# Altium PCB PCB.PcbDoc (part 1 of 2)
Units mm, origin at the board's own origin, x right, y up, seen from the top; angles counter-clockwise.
Board outline 85 x 56 mm, 4 copper layers (TOP, GND, SIG, BOTTOM), stack 1.586 mm thick; 75 components, 165 nets, 429 pads, 246 vias.
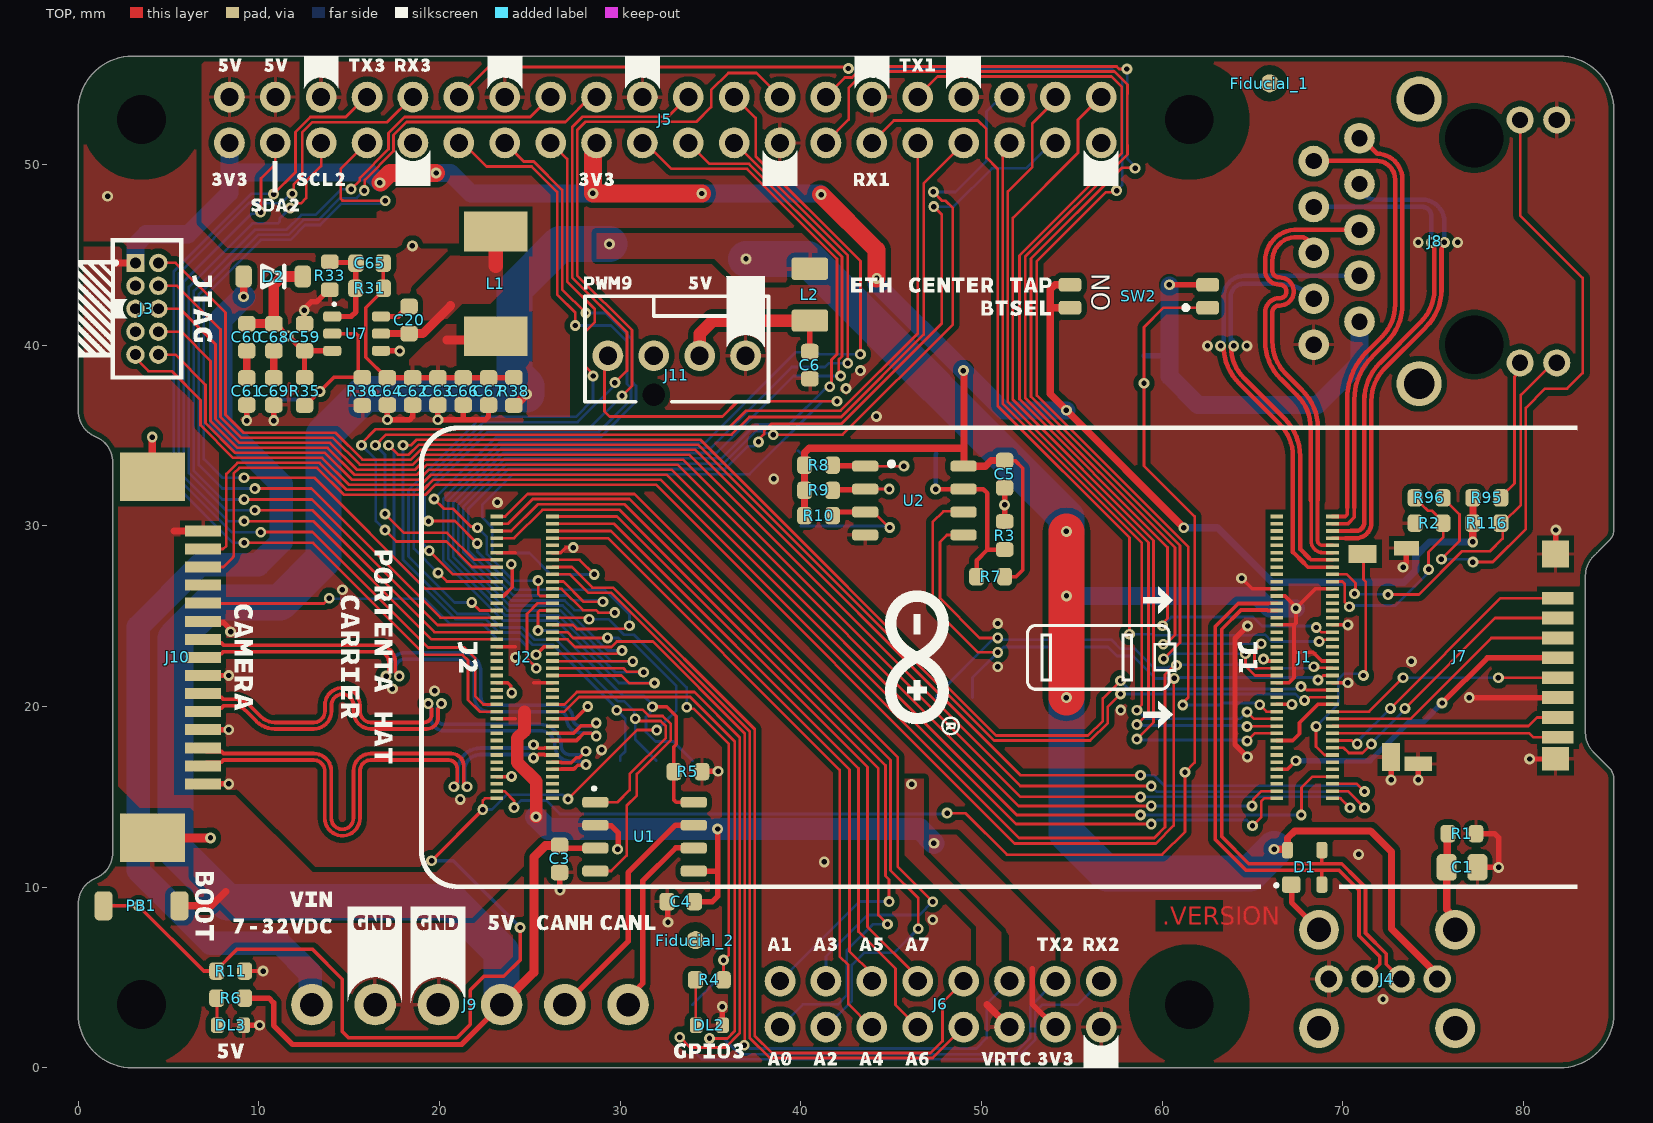
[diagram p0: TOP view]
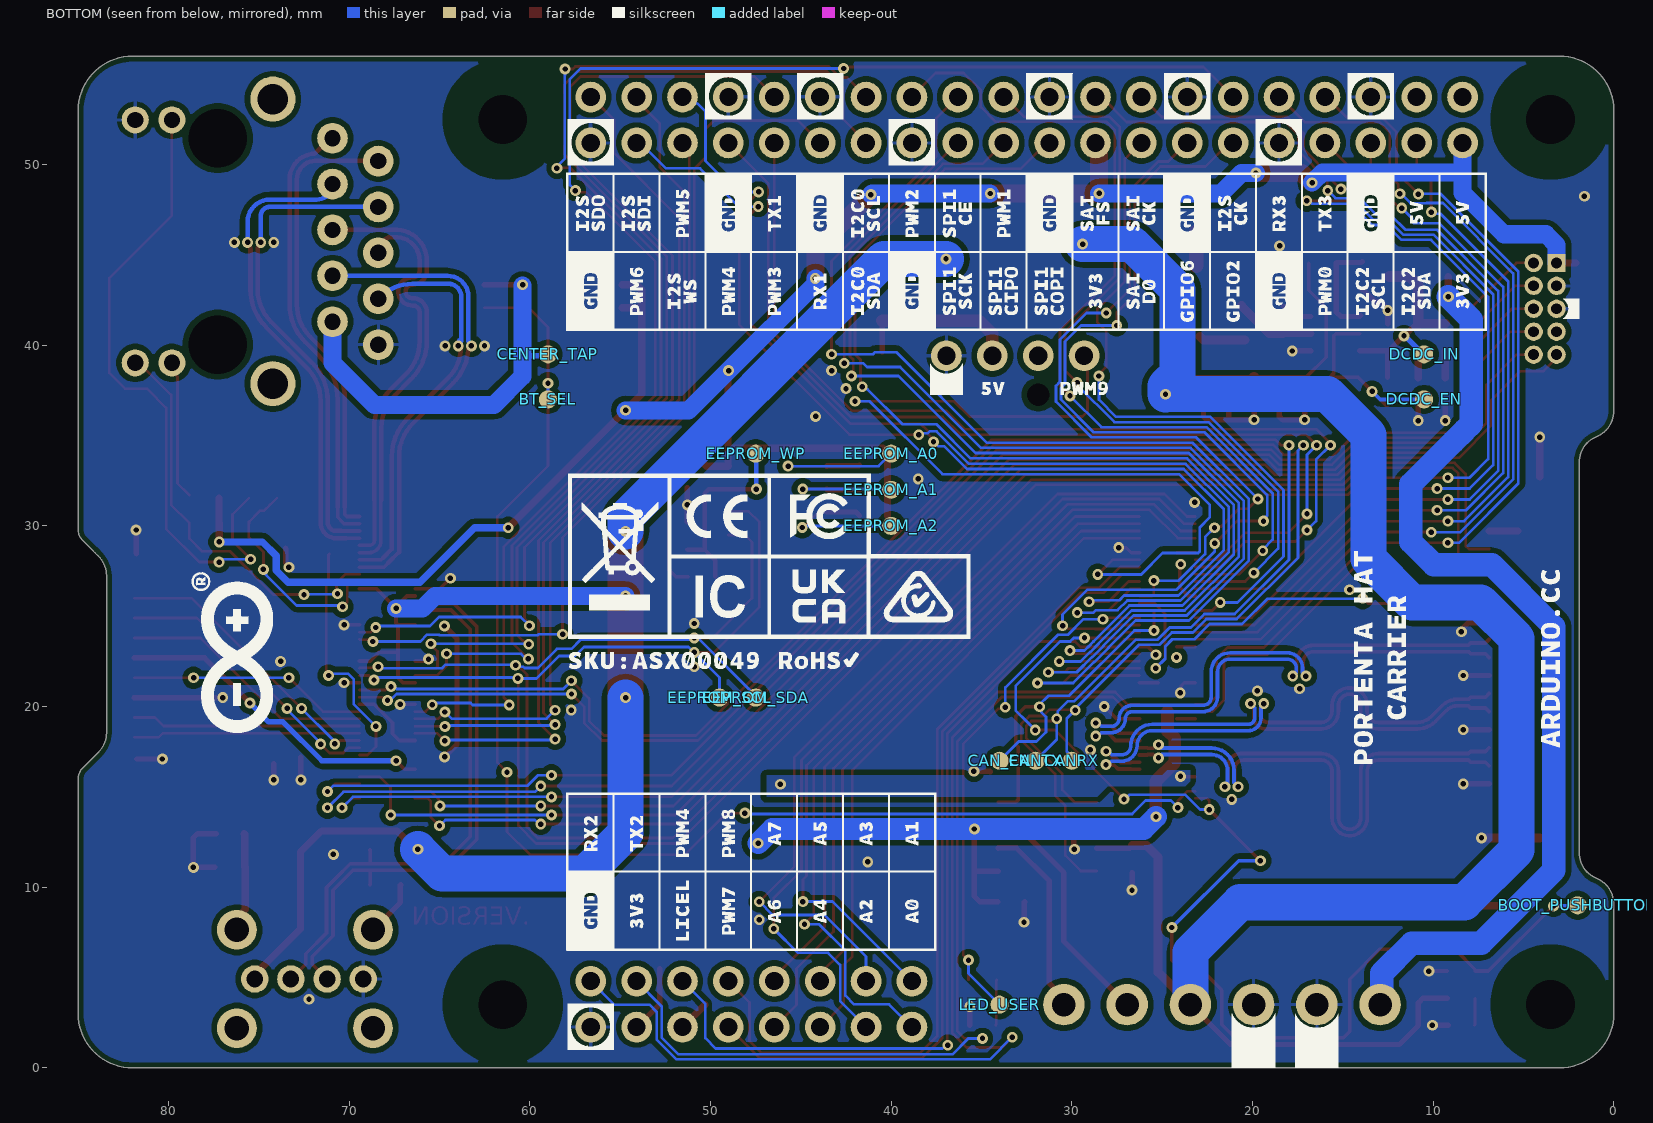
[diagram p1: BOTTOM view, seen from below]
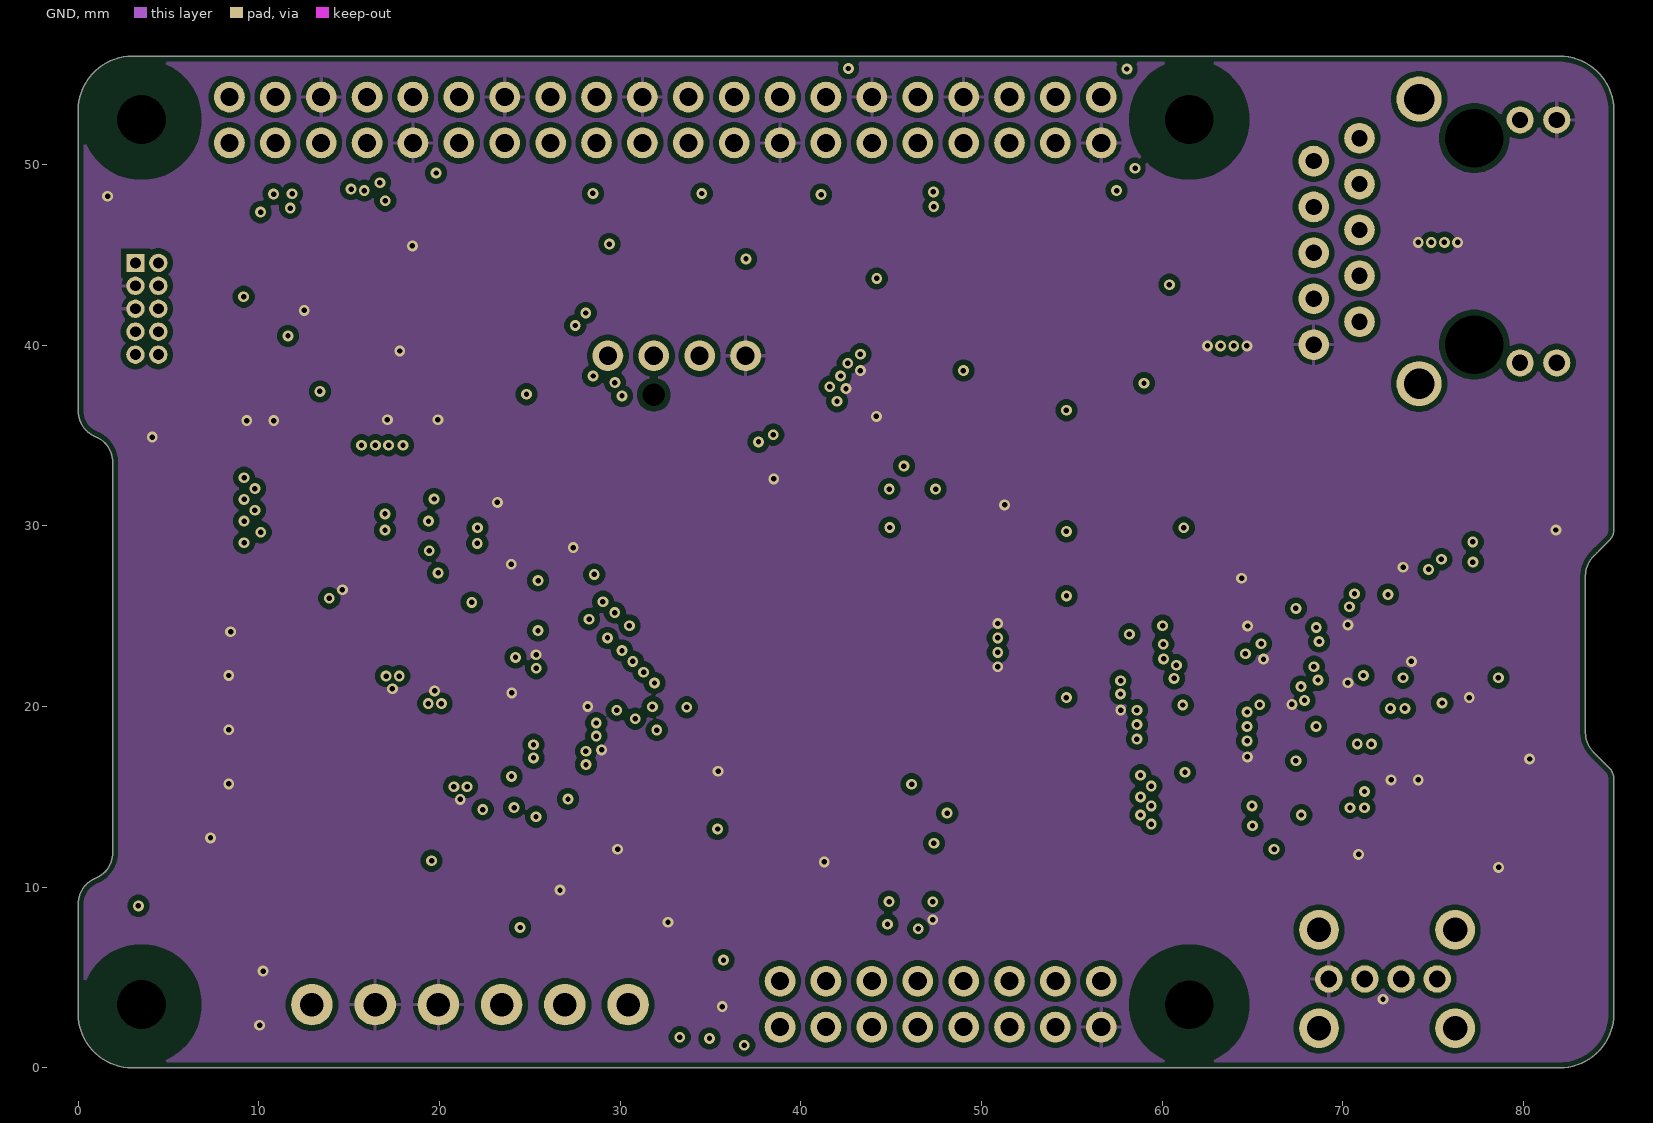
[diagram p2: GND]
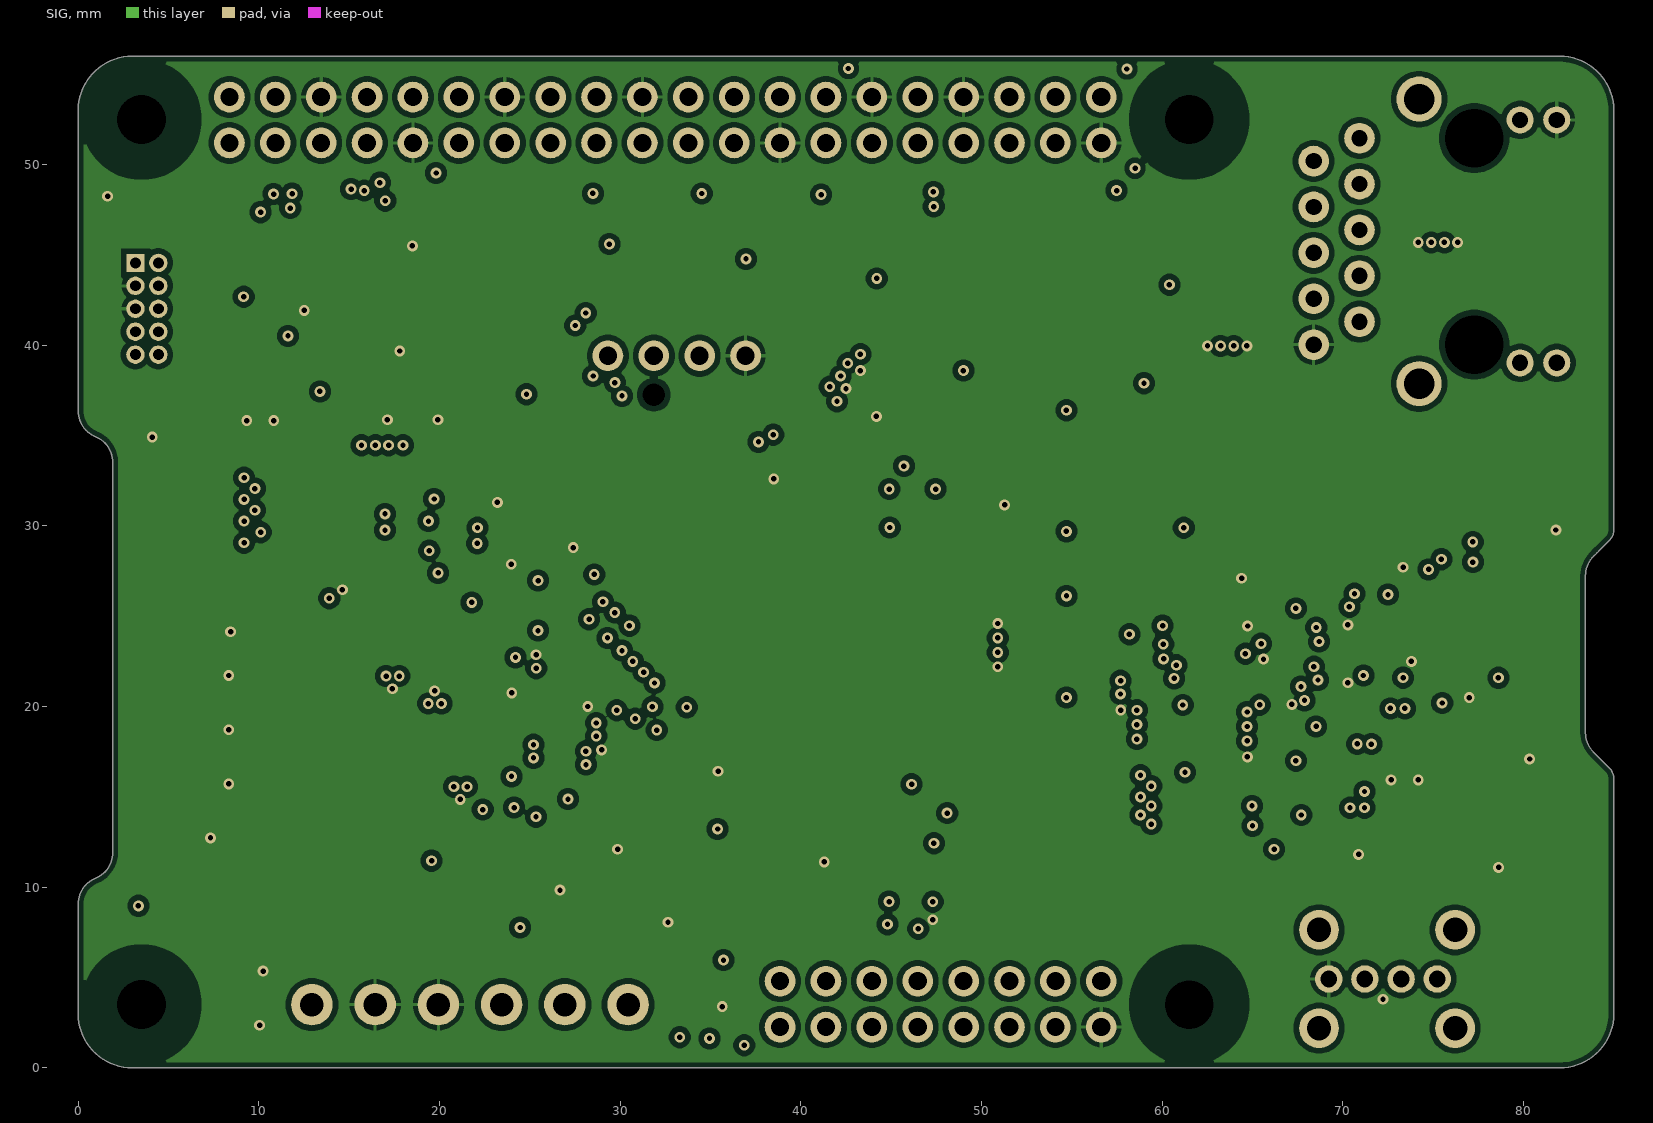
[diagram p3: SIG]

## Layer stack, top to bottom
Top Solder: solder mask 0.01, Solder Resist, Dk 3.5
TOP: signal copper 0.018
Dielectric 1: prepreg 0.14, PP-014, Dk 4.2
GND: signal copper 0.035
Dielectric2: core 1.2, FR-4, Dk 4.8
SIG: signal copper 0.035
Dielectric3: prepreg 0.14, PP-014, Dk 4.2
BOTTOM: signal copper 0.018
Bottom Solder: solder mask 0.01, Solder Resist, Dk 3.5

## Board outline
0,3 0,9.077 cw(c1.533,9.077) 0.959,10.499 ccw(c0.384,11.92) 1.917,11.92 1.917,33.52 ccw(c0.384,33.52) 0.959,34.941 cw(c1.533,36.363) 0,36.363 0,53 cw(c3,53) 3,56 82,56 82,55.999 cw(c82,52.999) 85,52.999 85,29.779 cw(c84.191,29.779) 84.763,29.207 84.251,28.695 84.065,28.509 83.879,28.323 ccw(c84.963,27.239) 83.43,27.239 83.43,18.559 ccw(c84.963,18.559) 83.879,17.475 84.763,16.591 cw(c84.191,16.019) 85,16.019 85,3 cw(c82,3) 82,0 3,0 cw(c3,3)

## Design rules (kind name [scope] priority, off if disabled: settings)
BoardOutlineClearance Mousebites [(ObjectKind = 'Pad') And (Name = 'Free-MOUSEBITE')] p1: gap=0 ignorepadtopadclearanceinfootprint=FALSE
BoardOutlineClearance eth_PAD [(ObjectKind = 'Pad') And (Name = 'J8-S2')] p2: gap=0.1 ignorepadtopadclearanceinfootprint=FALSE
BoardOutlineClearance Silks [(OnLayer('Top Overlay') OR OnLayer('Bottom Overlay'))] p3: gap=0 ignorepadtopadclearanceinfootprint=FALSE
BoardOutlineClearance [All] p4: gap=0.3 ignorepadtopadclearanceinfootprint=FALSE
Clearance Fixing [(ObjectKind = 'Pad') And (Layer = 'MultiLayer') And (Name = 'Free-FIXING')] p1: gap=2 ignorepadtopadclearanceinfootprint=FALSE
Clearance COPPER_0.3mm [All] p2: gap=0.127 ignorepadtopadclearanceinfootprint=TRUE except(0.3: Arc-Fill Arc-Poly Arc-Region Track-Fill Track-Poly Track-Region SMDPad-Fill SMDPad-Poly SMDPad-Region THPad-Fill THPad-Poly THPad-Region Via-Fill Via-Poly Via-Region Fill-Fill Fill-Poly Fill-Region Poly-Poly Poly-Region Region-Region)
Clearance "Generic clearance 0.15mm" [All] p3: gap=0.15 ignorepadtopadclearanceinfootprint=TRUE
ComponentClearance [All] p1: gap=0.2 collisioncheckmode=3 verticalgap=0 showdistances=TRUE
DiffPairsRouting ETH [InDifferentialPairClass('ETH')] p1: maxlimit=0.15 minlimit=0.15 mostfreqgap=0.15 toplayer_minwidth=0.15 toplayer_maxwidth=0.25 toplayer_prefwidth=0.25 midlayer1_minwidth=0.15 midlayer1_maxwidth=0.381 midlayer1_prefwidth=0.381 midlayer2_minwidth=0.15 midlayer2_maxwidth=0.381 midlayer2_prefwidth=0.381 bottomlayer_minwidth=0.15 bottomlayer_maxwidth=0.25 bottomlayer_prefwidth=0.25 maxuncoupledlength=12.7
DiffPairsRouting USB [InDifferentialPairClass('USB')] p2: maxlimit=0.25 minlimit=0.15 mostfreqgap=0.25 toplayer_maxgap=0.15 toplayer_prefgap=0.15 toplayer_minwidth=0.15 toplayer_maxwidth=0.21 toplayer_prefwidth=0.21 midlayer2_mingap=0.25 midlayer2_minwidth=0.15 midlayer2_maxwidth=0.15 midlayer2_prefwidth=0.15 bottomlayer_maxgap=0.15 bottomlayer_prefgap=0.15 bottomlayer_minwidth=0.15 bottomlayer_maxwidth=0.21 bottomlayer_prefwidth=0.21 impedanceprofiledriven=TRUE impedanceprofileid={065E212C-32C3-402A-8E5D-A34D7F87B9C8} impedanceprofilevalue=90.000000 maxuncoupledlength=12.7
DiffPairsRouting CAM [InDifferentialPairClass('CAMERA')] p3: maxlimit=0.25 minlimit=0.15 mostfreqgap=0.25 toplayer_maxgap=0.15 toplayer_prefgap=0.15 toplayer_minwidth=0.15 toplayer_maxwidth=0.21 toplayer_prefwidth=0.21 midlayer2_mingap=0.25 midlayer2_minwidth=0.15 midlayer2_maxwidth=0.15 midlayer2_prefwidth=0.15 bottomlayer_maxgap=0.15 bottomlayer_prefgap=0.15 bottomlayer_minwidth=0.15 bottomlayer_maxwidth=0.21 bottomlayer_prefwidth=0.21 impedanceprofiledriven=TRUE impedanceprofileid={065E212C-32C3-402A-8E5D-A34D7F87B9C8} impedanceprofilevalue=90.000000 maxuncoupledlength=12.7
Height [All] p1: minheight=0 maxheight=30 prefheight=12.7
HoleSize [All] p1: absolutevalues=TRUE maxlimit=30 minlimit=0.3 maxpercent=80.000 minpercent=20.000
HoleToHoleClearance [All] p1: gap=0.25 allowstackedmicrovias=FALSE
MatchedLengths CAM_DIFF [InDifferentialPairClass('CAMERA')] p1: tolerance=25.4 checknetsindiffpair=FALSE checkdiffpairvsdiffpair=TRUE checkxsignals=TRUE checkothers=TRUE usedelayunits=TRUE delaytolerance=30.000000
MatchedLengths ETH_DIFF [InDifferentialPairClass('ETH')] p2: tolerance=25.4 checknetsindiffpair=TRUE checkdiffpairvsdiffpair=FALSE checkxsignals=FALSE checkothers=FALSE usedelayunits=TRUE delaytolerance=10.000000
MatchedLengths ETH_group [InDifferentialPairClass('ETH')] p3: tolerance=25.4 checknetsindiffpair=FALSE checkdiffpairvsdiffpair=TRUE checkxsignals=TRUE checkothers=TRUE usedelayunits=TRUE delaytolerance=10.000000
MinimumAnnularRing [All] p1: minimumring=0.15
PlaneConnect [All] p1: pad.planeconnectstyle=Relief pad.reliefexpansion=0.508 pad.reliefentries=4 pad.reliefconductorwidth=0.254 pad.reliefairgap=0.254 via.planeconnectstyle=Direct via.reliefexpansion=0.508 via.reliefentries=4 via.reliefconductorwidth=0.254 via.reliefairgap=0.254
PolygonConnect [All] p1: thpad.connectstyle=Relief thpad.reliefconductorwidth=0.2 thpad.reliefentries=4 thpad.polygonreliefangle="90 Angle" thpad.airgapwidth=0.254 smdpad.connectstyle=Relief smdpad.reliefconductorwidth=0.2 smdpad.reliefentries=4 smdpad.polygonreliefangle="90 Angle" smdpad.airgapwidth=0.254 via.connectstyle=Direct via.reliefconductorwidth=0.254 via.reliefentries=4 via.polygonreliefangle="90 Angle" via.airgapwidth=0.254
RoomDefinition U_EEPROM [InComponentClass('U_EEPROM')] p1: confinementstyle=ConfineIn formatcopy=TRUE lockcomponents=FALSE outline 86.162,1.499 112.562,1.499 112.562,9.999 86.162,9.999
RoomDefinition U_CAMERA [InComponentClass('U_CAMERA')] p2: confinementstyle=ConfineIn formatcopy=TRUE lockcomponents=FALSE outline 86.162,0.399 94.562,0.399 94.562,25.899 86.162,25.899
RoomDefinition DCDC_CONVERTER [InComponentClass('DCDC_CONVERTER')] p3: confinementstyle=ConfineIn formatcopy=TRUE lockcomponents=FALSE outline 86.162,0.499 88.762,0.499 88.762,6.799 86.162,6.799
RoomDefinition U_CAN_PHY [InComponentClass('U_CAN_PHY')] p4: confinementstyle=ConfineIn formatcopy=TRUE lockcomponents=FALSE outline 86.162,1.499 88.562,1.499 88.562,4.099 86.162,4.099
RoomDefinition U_ETH_CONNECTOR [InComponentClass('U_ETH_CONNECTOR')] p5: confinementstyle=ConfineIn formatcopy=TRUE lockcomponents=FALSE outline 86.162,1.499 147.662,1.499 147.662,27.099 86.162,27.099
RoomDefinition U_SDcard [InComponentClass('U_SDcard')] p6: confinementstyle=ConfineIn formatcopy=TRUE lockcomponents=FALSE outline -25.538,-7.701 25.262,-7.701 25.262,17.699 -25.538,17.699
RoomDefinition "MICRO USB CONNECTOR" [InComponentClass('MICRO USB CONNECTOR')] p7: confinementstyle=ConfineIn formatcopy=TRUE lockcomponents=FALSE outline 66.762,22.299 84.462,22.299 84.462,33.799 66.762,33.799
RoomDefinition U_Headers [InComponentClass('U_Headers')] p8: confinementstyle=ConfineIn formatcopy=TRUE lockcomponents=FALSE outline 66.762,29.499 72.262,29.499 72.262,81.799 66.762,81.799
RoomDefinition TOP [InComponentClass('TOP')] p9: confinementstyle=ConfineIn formatcopy=TRUE lockcomponents=FALSE outline 66.762,18.299 83.662,18.299 83.662,29.399 66.762,29.399
RoomDefinition "HDConnectors FEMALE" [InComponentClass('HDConnectors FEMALE')] p10: confinementstyle=ConfineIn formatcopy=TRUE lockcomponents=FALSE outline -25.538,-7.701 25.262,-7.701 25.262,17.699 -25.538,17.699
RoutingVias StandardVias [All] p1: holewidth=0.3 width=0.6 viastyle="Through Hole" minholewidth=0.3 minwidth=0.6 maxholewidth=0.3 maxwidth=0.6
SilkToSilkClearance [All] p1: silktosilkclearance=0.2
SilkToSolderMaskClearance [IsPad] p1: minsilkscreentomaskgap=0.15 clearancetoexposedcopper=TRUE
SolderMaskExpansion VIAtented [IsVia] p1: expansion=0.102 istentingtop=TRUE
SolderMaskExpansion [All] p2: expansion=0.05 istentingtop=FALSE
UnConnectedPin [All] p1:
UnRoutedNet [All] p1: checkbadconnections=TRUE
ViasUnderSMD [All] p1: allowed=FALSE
Width StandardTraces [All] p1: maxlimit=5 minlimit=0.15 preferedwidth=0.15
21 further rules are at their usual default settings.

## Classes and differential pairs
component class U_EEPROM: C5 EEPROM_A0 EEPROM_A1 EEPROM_A2 EEPROM_SCL EEPROM_SDA EEPROM_WP R3 R7 R8 R9 R10 U2
net class SD: CD CLK CMD d0 D1 D2 D3
net class CAM: CAM.CK_1_N CAM.CK_1_P CAM.D0_1_N CAM.D0_1_P CAM.D1_1_N CAM.D1_1_P
net class ANALOG: A0_1 A1_1 A2_1 A3_1 A4_1 A5_1 A6_1 A7_1
differential pair class CAMERA: CAM.CK_1 CAM.D0_1 CAM.D1_1
component class U_CAMERA: J10
component class U_CAN_PHY: C3 C4 CAN_EN CANRX CANTX R5 U1
component class DCDC_CONVERTER: C20 C59 C60 C61 C62 C63 C64 C65 C66 C67 C68 C69 D2 DCDC_EN DCDC_IN L1 R31 R33 R35 R36 R38 U7
component class U_ETH_CONNECTOR: J8 R2 R95 R96 R116
component class U_SDcard: J7
component class "MICRO USB CONNECTOR": C1 D1 J4 R1
differential pair class USB: CARRIER_USB.D_1 PORTENTA_USB.D_1 USB0_D USB1_D
differential pair class PCIE: PCIE_CK PCIE_RX PCIE_TX
differential pair class ETH: ETH_A ETH_B ETH_C ETH_D
differential pair class DSI: DSI_CK DSI_D0 DSI_D1 DSI_D2 DSI_D3
component class U_Headers: J5
component class TOP: BOOT_PUSHBUTTON BT_SEL C6 CENTER_TAP DL2 DL3 Fiducial_1 Fiducial_2 J3 J6 J9 J11 L2 LED_USER PB1 R4 R6 R11 SW2
component class "HDConnectors FEMALE": J1 J2
differential pair CAM.D1_1: +CAM.D1_1_P -CAM.D1_1_N
differential pair CAM.D0_1: +CAM.D0_1_P -CAM.D0_1_N
differential pair CAM.CK_1: +CAM.CK_1_P -CAM.CK_1_N
differential pair USB0_D: +USB0_D_P -USB0_D_N
differential pair USB1_D: +USB1_D_P -USB1_D_N
differential pair PCIE_TX: +PCIE_TX_P -PCIE_TX_N
differential pair PCIE_RX: +PCIE_RX_P -PCIE_RX_N
differential pair PCIE_CK: +PCIE_CK_P -PCIE_CK_N
differential pair ETH_D: +ETH_D_P -ETH_D_N
differential pair ETH_C: +ETH_C_P -ETH_C_N
differential pair ETH_B: +ETH_B_P -ETH_B_N
differential pair ETH_A: +ETH_A_P -ETH_A_N
differential pair DSI_D3: +DSI_D3_P -DSI_D3_N
differential pair DSI_D2: +DSI_D2_P -DSI_D2_N
differential pair DSI_D1: +DSI_D1_P -DSI_D1_N
differential pair DSI_D0: +DSI_D0_P -DSI_D0_N
differential pair DSI_CK: +DSI_CK_P -DSI_CK_N

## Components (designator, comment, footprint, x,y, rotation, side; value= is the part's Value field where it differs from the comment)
BOOT_PUSHBUTTON "CMP-018-0005-A.3" TP-1.00MM 2,9 r90 bottom
BT_SEL "CMP-018-0005-A.3" TP-1.00MM 59,37 r90 bottom
C1 "FV21X472K102ECG" CAP-0805 76.6,11.101 r180 top value=4.7nF
C3 "0603B104K500CT" CAP-0603 26.646,11.565 r270 top value=100nF
C4 "0603B104K500CT" CAP-0603 33.35,9.2 r180 top value=100nF
C5 "0603B104K500CT" CAP-0603 51.28,32.866 r270 top value=100nF
C6 "C1608A106M250NT" CAP-0603 40.5,38.9 r90 top value=10µF
C20 "0603B104K500CT" CAP-0603 18.312,41.394 r270 top value=100nF
C59 "0603B104K500CT" CAP-0603 12.528,40.444 r90 top value=100nF
C60 "C1608A106M250NT" CAP-0603 9.328,40.444 r90 top value=10µF
C61 "C1608A106M250NT" CAP-0603 9.328,37.444 r90 top value=10µF
C62 "C1608A106M250NT" CAP-0603 18.512,37.444 r90 top value=10µF
C63 "C1608A106M250NT" CAP-0603 19.912,37.444 r90 top value=10µF
C64 "0603B104K500CT" CAP-0603 17.112,37.444 r270 top value=100nF
C65 "C0603C101K2RAC7867" CAP-0603 16.128,44.544 r0 top value=100pF
C66 "C1608A106M250NT" CAP-0603 21.312,37.444 r90 top value=10µF
C67 "C1608A106M250NT" CAP-0603 22.712,37.444 r90 top value=10µF
C68 "C1608A106M250NT" CAP-0603 10.828,40.444 r90 top value=10µF
C69 "C1608A106M250NT" CAP-0603 10.828,37.444 r90 top value=10µF
CAN_EN "CMP-018-0005-A.3" TP-1.00MM 34,17 r90 bottom
CANRX "CMP-018-0005-A.3" TP-1.00MM 30,17 r90 bottom
CANTX "CMP-018-0005-A.3" TP-1.00MM 32,17 r90 bottom
CENTER_TAP "CMP-018-0005-A.3" TP-1.00MM 59,39.5 r90 bottom
D1 "PRTR5V0U2X,215" SOT190P230X110-4N 67.893,11.101 r0 top
D2 "PMEG6020AELRX" SOD123-1 10.793,43.806 r180 top
DCDC_EN "CMP-018-0005-A.3" TP-1.00MM 10.5,37 r90 bottom
DCDC_IN "CMP-018-0005-A.3" TP-1.00MM 10.5,39.5 r90 bottom
DL2 "HSMD-C190" LEDC1608X80N-AK 34.937,2.36 r180 top
DL3 "HSMG-C190" LEDC1608X80N-AK 8.437,2.36 r180 top
EEPROM_A0 "CMP-018-0005-A.3" TP-1.00MM 40,34 r0 bottom
EEPROM_A1 "CMP-018-0005-A.3" TP-1.00MM 40,32 r0 bottom
EEPROM_A2 "CMP-018-0005-A.3" TP-1.00MM 40,30 r0 bottom
EEPROM_SCL "CMP-018-0005-A.3" TP-1.00MM 49.5,20.5 r0 bottom
EEPROM_SDA "CMP-018-0005-A.3" TP-1.00MM 47.5,20.5 r0 bottom
EEPROM_WP "CMP-018-0005-A.3" TP-1.00MM 47.5,34 r0 bottom
Fiducial_1 "Fiducial mark 1mm with 2mm solder" "Fiducial mark 1mm with circle-Footprint-1" 65.95,54.5 r90 top
Fiducial_2 "Fiducial mark 1mm with 2mm solder" "Fiducial mark 1mm with circle-Footprint-1" 34.162,7.07 r90 top
J1 "DF40HC(4.0)-80DS-0.4V(51)-LEFT" DF40HC(4.0)-80DS-0.4V(51) 67.893,22.72 r270 top locked
J2 "DF40HC(4.0)-80DS-0.4V(51)-RIGHT" DF40HC(4.0)-80DS-0.4V(51) 24.713,22.72 r90 top locked
J3 "HPH2-A-10-SGA" PINHEAD_2X05_127 3.8,42.02 r0 top
J4 "22TW-476" 22TW-476 72.225,4.92 r90 top
J5 "PH2-40-UA" "PIN HEADER 2.54mm VERT. 2x20POS" 32.5,52.47 r0 top locked
J6 "PH2-16-UA" "PIN HEADER 2.54mm VERT. 2x8POS" 47.74,3.53 r0 top locked
J7 "114-00841-68" AMPHENOL_114-00841-68 76.012,22.799 r90 top locked
J8 "TRJG16414AENL" TRJG16414AENL 75.115,45.75 r90 top locked
J9 "22TW-277 6 PIN" "22TW-277 6 PIN" 21.687,3.501 r0 top locked
J10 "1-84953-5" 1-84952-5-Footprint-1 4.1,22.72 r270 top locked
J11 "47053-1000" 47053-1000-Footprint-1 33.13,39.42 r0 top
L1 "PMF63-103MT" PMF63 23.112,43.394 r270 top
L2 "LB3218T470K" INDC3218X20N 40.5,42.8 r270 top
LED_USER "CMP-018-0005-A.3" TP-1.00MM 34,3.501 r90 bottom
PB1 "IT-1185AP1C-160G-GTR" C&K_PTS820_NO_HOLES-1 3.5,8.97 r0 top
R1 "CRCW06031M00FKEA" RES-0603 76.596,12.965 r180 top value=1M
R2 "CRCW060310K0JNEAC" RES-0603 74.775,30.15 r180 top value=10k
R3 "CRCW06030000Z0EAC" RES-0603 51.28,29.466 r270 top value=0
R4 "CRCW0603470RFKEAC" RES-0603 34.937,4.87 r0 top value=470
R5 "CRCW0603100KFKEAC" RES-0603 33.75,16.4 r180 top value=100k
R6 "CRCW0603470RFKEAC" RES-0603 8.437,3.86 r0 top value=470
R7 "CRCW0603100KFKEAC" RES-0603 50.505,27.191 r0 top value=100k
R8 "CRCW06030000Z0EAC" RES-0603 40.98,33.366 r180 top value=0
R9 "CRCW06030000Z0EAC" RES-0603 40.98,31.966 r180 top value=0
R10 "CRCW06030000Z0EAC" RES-0603 40.98,30.566 r180 top value=0
R11 "CRCW0603470RFKEAC" RES-0603 8.437,5.36 r180 top value=470
R31 "CRCW0603100KFKEAC" RES-0603 16.128,43.144 r180 top value=100k
R33 "CRCW060319K1FKEAC" RES-0603 13.928,43.844 r90 top value=19.1k
R35 "CRCW060319K1FKEAC" RES-0603 12.528,37.444 r270 top value=19.1k
R36 "AC0603FR-134K7L" RES-0603 15.728,37.444 r270 top value=4.7k
R38 "CRCW06030000Z0EAC" RES-0603 24.112,37.444 r270 top value=0
R95 "CRCW0603470RFKEAC" RES-0603 77.975,31.55 r180 top value=470
R96 "CRCW0603470RFKEAC" RES-0603 74.775,31.55 r180 top value=470
R116 "CRCW060310K0JNEAC" RES-0603 77.975,30.15 r180 top value=10k
SW2 "218-2LPSTRF" CTS-218-2LPST_V 58.71,42.716 r180 top
U1 "TJA1049T/3J" TJA1049T_3J-Footprint-1 31.35,12.8 r0 top
U2 "CAT24C32WI-GT3" SOIC8 46.287,31.404 r0 top
U7 "AP63200WU-7" SOT95P280X100-6N 15.412,40.644 r0 top

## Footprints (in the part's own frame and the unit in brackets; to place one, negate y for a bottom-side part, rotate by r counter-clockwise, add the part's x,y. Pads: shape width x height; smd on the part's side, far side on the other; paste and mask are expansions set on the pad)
1-84952-5-Footprint-1 [mm]
  rect 0.61x2 smd mask+0.05: 1(7,2.8) 2(6,2.8) 3(5,2.8) 4(4,2.8) 5(3,2.8) 6(2,2.8) 7(1,2.8) 8(0,2.8) 9(-1,2.8) 10(-2,2.8) 11(-3,2.8) 12(-4,2.8) 13(-5,2.8) 14(-6,2.8) 15(-7,2.8)
  rect 2.68x3.6 smd mask+0.05: FIX(-9.99,0) FIX(9.99,0)
  body extent -11.46,-3.64 11.46,2.9, height 2.59
"22TW-277 6 PIN" [mm]
  round 2.3 hole 1.3: 1(-8.75,0) 2(-5.25,0) 3(-1.75,0) 4(1.75,0) 5(5.25,0) 6(8.75,0)
  body extent -10.98,-3.75 11,3.25, height 8.31
22TW-476 [mm]
  round 1.52 hole 0.92 mask+0.05: 1(0,-3) 2(0,-1) 3(0,1) 4(0,3)
  round 2.2 hole 1.35: 5(2.72,-3.99) 6(2.72,3.54) 7(-2.72,3.54) 8(-2.72,-3.99)
  body extent -3.56,-15.53 3.56,4.07, height 14.65
47053-1000-Footprint-1 [mm]
  round 1.7 hole 1 paste-100 mask+0.05: 1(-3.81,0) 2(-1.27,0) 3(1.27,0) 4(3.81,0)
  round 1 hole 1.25 unplated paste-100 mask+0.05: NC(-1.27,-2.16)
  silkscreen extent -5.08,-2.54 5.08,3.3, body extent -5.1,-2.54 5.1,3.3, height 10.05
AMPHENOL_114-00841-68 [mm]
  rect 0.7x1.75 smd mask+0.05: 1(3.2,-5.888) 2(2.1,-5.888) 3(1,-5.888) 4(-0.1,-5.888) 5(-1.2,-5.888) 6(-2.3,-5.888) 7(-3.4,-5.888) 8(-4.5,-5.888)
  rect 1x1.55 smd mask+0.05: CD1(5.65,4.912)
  rect 1.55x1 smd mask+0.05: CD2(-5.602,3.337)
  rect 1.3x1.5 smd mask+0: SH1(-5.7,-5.76)
  rect 1.5x1.5 smd mask+0: SH2(5.65,-5.76)
  rect 0.8x1.4 smd mask+0.05: SH3(5.975,2.487)
  rect 0.8x1.5 smd mask+0.05: SH4(-5.975,1.837)
  body extent -6,-10.29 6,4.99, height 1.6
C&K_PTS820_NO_HOLES-1 [mm]
  rrect49% 1x1.6 smd mask+0.05: 1(-2.1,0) 2(2.1,0)
  body extent -2.25,-1.45 2.25,1.45, height 2
CAP-0603 [mm] "Chip Capacitor, Body 0603 imperial,1.6x0.8mm, IPC High Density"
  rrect51% 0.87x0.97 smd mask+0.05: 1(-0.75,0) 2(0.75,0)
  body extent -0.8,-0.4 0.8,0.4, height 0.8
CAP-0805 [mm] "Chip Capacitor, Body 0805 imperial, 2.0x1.2mm, IPC Medium Density"
  rrect45% 1.11x1.47 smd mask+0.05: 1(-0.85,0) 2(0.85,0)
  body extent -1,-0.62 1,0.63, height 1.25
CTS-218-2LPST_V [mm] "SMD, 4-Leads, Body 5.8x3.71mm, Pitch 1.27mm"
  rrect50% 1.27x0.76 smd: 1(-3.81,0.635) 2(-3.81,-0.635) 3(3.81,-0.635) 4(3.81,0.635)
  silkscreen extent -2.7,0.54 -2.5,0.73, body extent -4.22,-1.85 4.22,1.86, height 2.5
DF40HC(4.0)-80DS-0.4V(51) [mm]
  rect 0.2x0.7 smd mask+0: 1(-7.8,1.54) 2(-7.8,-1.54) 3(-7.4,1.54) 4(-7.4,-1.54) 5(-7,1.54) 6(-7,-1.54) 7(-6.6,1.54) 8(-6.6,-1.54) 9(-6.2,1.54) 10(-6.2,-1.54) 11(-5.8,1.54) 12(-5.8,-1.54) 13(-5.4,1.54) 14(-5.4,-1.54) 15(-5,1.54) 16(-5,-1.54) 17(-4.6,1.54) 18(-4.6,-1.54) 19(-4.2,1.54) 20(-4.2,-1.54) 21(-3.8,1.54) 22(-3.8,-1.54) 23(-3.4,1.54) 24(-3.4,-1.54) 25(-3,1.54) 26(-3,-1.54) 27(-2.6,1.54) 28(-2.6,-1.54) 29(-2.2,1.54) 30(-2.2,-1.54) 31(-1.8,1.54) 32(-1.8,-1.54) 33(-1.4,1.54) 34(-1.4,-1.54) 35(-1,1.54) 36(-1,-1.54) 37(-0.6,1.54) 38(-0.6,-1.54) 39(-0.2,1.54) 40(-0.2,-1.54) 41(0.2,1.54) 42(0.2,-1.54) 43(0.6,1.54) 44(0.6,-1.54) 45(1,1.54) 46(1,-1.54) 47(1.4,1.54) 48(1.4,-1.54) 49(1.8,1.54) 50(1.8,-1.54) 51(2.2,1.54) 52(2.2,-1.54) 53(2.6,1.54) 54(2.6,-1.54) 55(3,1.54) 56(3,-1.54) 57(3.4,1.54) 58(3.4,-1.54) 59(3.8,1.54) 60(3.8,-1.54) 61(4.2,1.54) 62(4.2,-1.54) 63(4.6,1.54) 64(4.6,-1.54) 65(5,1.54) 66(5,-1.54) 67(5.4,1.54) 68(5.4,-1.54) 69(5.8,1.54) 70(5.8,-1.54) 71(6.2,1.54) 72(6.2,-1.54) 73(6.6,1.54) 74(6.6,-1.54) 75(7,1.54) 76(7,-1.54) 77(7.4,1.54) 78(7.4,-1.54) 79(7.8,1.54) 80(7.8,-1.54)
  body extent -9.3,-1.69 9.3,1.69, height 3.89
"Fiducial mark 1mm with circle-Footprint-1" [mm]
  round 1 smd paste-10 mask+0.5: 1(0,0)
  TOP pour cut-out: 0,1 0.383,0.924 0.707,0.707 0.924,0.383 1,0 1,0 0.924,-0.383 0.707,-0.707 0.383,-0.924 0,-1 0,-1 -0.383,-0.924 -0.707,-0.707 -0.924,-0.383 -1,0 -1,0 -0.924,0.383 -0.707,0.707 -0.383,0.924 0,1
INDC3218X20N [mm] "Chip Inductor, 2-Leads, Body 3,20x1,80mm, IPC Medium Density"
  rrect25% 1.23x2.02 smd: 1(-1.435,0) 2(1.435,0)
  body extent -1.7,-1 1.7,1, height 2
LEDC1608X80N-AK [mm]
  rrect50% 0.72x0.87 smd: A(0.725,0) C(-0.725,0)
  body extent -0.8,-0.4 0.8,0.4, height 0.79
"PIN HEADER 2.54mm VERT. 2x8POS" [mm]
  round 1.7 hole 1 mask+0.2: 1(-8.89,-1.27) 2(-8.89,1.27) 3(-6.35,-1.27) 4(-6.35,1.27) 5(-3.81,-1.27) 6(-3.81,1.27) 7(-1.27,-1.27) 8(-1.27,1.27) 9(1.27,-1.27) 10(1.27,1.27) 11(3.81,-1.27) 12(3.81,1.27) 13(6.35,-1.27) 14(6.35,1.27) 15(8.89,-1.27) 16(8.89,1.27)
  body extent -10.16,-2.54 10.16,2.54, height 9.5
"PIN HEADER 2.54mm VERT. 2x20POS" [mm]
  round 1.7 hole 1 mask+0.2: 1(-24.13,-1.27) 2(-24.13,1.27) 3(-21.59,-1.27) 4(-21.59,1.27) 5(-19.05,-1.27) 6(-19.05,1.27) 7(-16.51,-1.27) 8(-16.51,1.27) 9(-13.97,-1.27) 10(-13.97,1.27) 11(-11.43,-1.27) 12(-11.43,1.27) 13(-8.89,-1.27) 14(-8.89,1.27) 15(-6.35,-1.27) 16(-6.35,1.27) 17(-3.81,-1.27) 18(-3.81,1.27) 19(-1.27,-1.27) 20(-1.27,1.27) 21(1.27,-1.27) 22(1.27,1.27) 23(3.81,-1.27) 24(3.81,1.27) 25(6.35,-1.27) 26(6.35,1.27) 27(8.89,-1.27) 28(8.89,1.27) 29(11.43,-1.27) 30(11.43,1.27) 31(13.97,-1.27) 32(13.97,1.27) 33(16.51,-1.27) 34(16.51,1.27) 35(19.05,-1.27) 36(19.05,1.27) 37(21.59,-1.27) 38(21.59,1.27) 39(24.13,-1.27) 40(24.13,1.27)
  body extent -25.4,-2.54 25.4,2.54, height 9.5
PINHEAD_2X05_127 [mil]
  rect 38.73x38.73 / inner rect 38.74x38.74 / far side rect 38.73x38.73 hole 23.62: 1(-25,100)
  round 40 hole 23.62: 2(25,100) 3(-25,50) 4(25,50) 5(-25,0) 6(25,0) 7(-25,-50) 8(25,-50) 9(-25,-100) 10(25,-100)
  silkscreen extent -70,98 -67,102, body extent -68,-125 68,125, height 158
PMF63 [mm] "PMF63 K-WELL"
  rect 2.2x3.5 smd paste-0.142 mask+0.05: 1(-2.9,0) 2(2.9,0)
  body extent -3.45,-3.45 3.45,3.45, height 3.05
RES-0603 [mm] "Chip Resistor - Body 0603 imperial,1.6x0.8mm, IPC High Density"
  rrect51% 0.82x0.97 smd mask+0.05: 1(-0.775,0) 2(0.775,0)
  body extent -0.8,-0.4 0.8,0.4, height 0.43
SOD123-1 [mm]
  rrect50% 0.91x1.22 smd: A(1.635,0) C(-1.635,0)
  silkscreen extent -0.6,-0.6 0.6,0.6, body extent -1.85,-1 1.85,1, height 1.2
SOIC8 [mm] "SOIC, 8-Leads, Body 4.90x3.90mm, Pitch 1.27mm, Thermal Pad 3.00x2.50mm, IPC Medium Density"
  rrect50% 1.45x0.6 smd mask+0.05: 1(-2.725,1.905) 2(-2.725,0.635) 3(-2.725,-0.635) 4(-2.725,-1.905) 5(2.725,-1.905) 6(2.725,-0.635) 7(2.725,0.635) 8(2.725,1.905)
  silkscreen extent -1.39,1.91 -1.14,2.16, body extent -3,-2.5 3,2.5, height 1.75
SOT95P280X100-6N [mm] "SOT23, 6-Leads, Body 2,90x2,80mm, Pitch 0,95mm, IPC Medium Density"
  rrect50% 1x0.55 smd mask+0.05: 1(-1.35,0.95) 2(-1.35,0) 3(-1.35,-0.95) 4(1.35,-0.95) 5(1.35,0) 6(1.35,0.95)
  silkscreen extent -1.29,1.58 -1.19,1.68, body extent -1.4,-1.5 1.4,1.5, height 1
SOT190P230X110-4N [mm]
  rrect33% 1.01x0.91 smd paste+0 mask+0.05: 1(-0.75,-0.955)
  rrect49% 0.61x0.91 smd paste+0 mask+0.05: 2(0.95,-0.955) 3(0.95,0.955) 4(-0.95,0.955)
  silkscreen extent -1.62,-1.05 -1.52,-0.95, body extent -1.45,-1.15 1.45,1.15, height 1
TJA1049T_3J-Footprint-1 [mm]
  rrect50% 1.45x0.6 smd: 1(-2.725,1.905) 2(-2.725,0.635) 3(-2.725,-0.635) 4(-2.725,-1.905) 5(2.725,-1.905) 6(2.725,-0.635) 7(2.725,0.635) 8(2.725,1.905)
  silkscreen extent -2.84,2.62 -2.74,2.72, body extent -3,-2.5 3,2.5, height 1.75
TP-1.00MM [mm]
  rrect100% 1x1 smd paste-2.54: X(0,0)
TRJG16414AENL [mm]
  round 1.7 hole 0.9 paste-100 mask+0.05: 1(-5.715,6.73) 2(-4.445,4.19) 3(-3.175,6.73) 4(-1.905,4.19) 5(-0.635,6.73) 6(0.635,4.19) 7(1.905,6.73) 8(3.175,4.19) 9(4.445,6.73) 10(5.715,4.19)
  round 1.5 hole 0.9 paste-100 mask+0.05: 11(6.725,-4.7) 12(6.725,-6.73) 13(-6.725,-4.7) 14(-6.725,-6.73)
  round 1.5 hole 3.25 unplated paste-100 mask+0.05: NC(-5.715,-2.16) NC1(5.715,-2.16)
  round 2.5 hole 1.7 paste-100 mask+0.05: SH1(-7.875,0.89) SH2(7.875,0.89)
  body extent -9.55,-12.96 9.55,8.34, height 15.08

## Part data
BOOT_PUSHBUTTON BT_SEL CAN_EN CANRX CANTX CENTER_TAP DCDC_EN DCDC_IN EEPROM_A0 EEPROM_A1 EEPROM_A2 EEPROM_SCL EEPROM_SDA EEPROM_WP LED_USER: library part UT0013-A.4, "Test point 1.00mm"
C1: library part C0059-A.14, "CAP CHIP 0805 4.7nF 10% 1000V X7R", Case Code (Imperial)=0805, Dielectric=X7R, Manufacturer="PSA Shenzen", Manufacturer 2=KEMET, Part number 2=C0805V472KDRACTU, Part number 3=C0805C472KDRACTU, Tolerance=10%, Voltage=1kV
C3 C4 C5 C20 C59 C64: library part C0043-A.14, "CAP CHIP 0603 100nF 10% 50V X7R", Case Code (Imperial)=0603, Dielectric=X7R, Manufacturer=Walsin, Manufacturer 2=Hottech, Manufacturer 3="Samsung Electro-Mechanics", Part number 2=C1608B104K500NT, Part number 3=CL10B104KB8NNNC, Tolerance=10%, Voltage=50V
C6 C60 C61 C62 C63 C66 C67 C68 C69: library part C0047-A.18, "CAP CHIP 0603 10uF 20% 25V X5R", Case Code (Imperial)=0603, Dielectric=X5R, Manufacturer=Hottech, Manufacturer 2="Murata Electronics", Part number 2=CL10A106MA8NRNC, Tolerance=20%, Voltage=25V
C65: library part C0081-A.12, "CAP CHIP 0603 100pF 10% 200V X7R", Case Code (Imperial)=0603, Dielectric=X7R, Manufacturer=KEMET, Tolerance=10%, Voltage=200V
D1: library part D0025-A.5, "TVS ARRAY 4LIN.8kV 1pF SOT143B", Manufacturer=Nexperia
D2: library part D0026-A.6, "DIODE SCHOTTKY SMD 2A 60V SOD123FL", Forward Current=2A, Forward Voltage=0.6V, Manucturer Part Number 2=SS26L, Manufacturer=Nexperia
DL2: library part L0007-A.8, "LED SMD 0603 ORANGE604 8mcd DIFF.", Manufacturer=Broadcom
DL3: library part L0009-A.5, "LED SMD 0603 GREEN/568 15mcd 120^", Manufacturer=Broadcom
Fiducial_1 Fiducial_2: library part UT0024-A.6
J1: library part J0155-A.6, "CONN RCPT FEMALE D80POS 0.4MM SMD GOLD", Current Rating=300mA, Manufacturer=Hirose, Package Quantity=1, Part Number=DF40HC(4.0)-80DS-0.4V(51), Voltage Rating=30V
J2: library part J0156-A.5, "CONN RCPT FEMALE D80POS 0.4MM SMD GOLD", Current Rating=300mA, Manufacturer=Hirose, Package Quantity=1, Part Number=DF40HC(4.0)-80DS-0.4V(51), Voltage Rating=30V
J3: library part J0068-A.9, "CONN CONN STRIP THD 1,27 M/2/D 10v AuF H6,3 JTAG", Manufacturer="Adam Tech"
J4: library part J0334-A.4, "CONN USB A 2.0 RECEPTACLE RIGHT ANGLE", Manufacturer=4UCONN
J5: library part J0326-A.3, "HEADER TH 2.54mm VERT. MALE 2x20POS", Manufacturer="Adam Tech"
J6: library part J0327-A.2, "HEADER TH 2.54mm VERT. MALE 2x8POS", Manufacturer="Adam Tech"
J7: library part J0011-A.5, "CONN Micro SD", Manufacturer=Amphenol
J8: library part J0354-A.2, "CONN ETH RJ45 TH 10/100/1000 integrated magnetics LED green LED yellow 21.25x15.95x13.45mm", Manufacturer=TRXCOM
J9: library part J0319-A.3, "CONN SCREW TERMINAL 22TW-277 6 PIN", Manufacturer="4U CON", Max Current Rating=10A
J10: library part J0320-A.3, "CONN FFC/FPC Connector, 15 Contact(s), 1 Row(s), TOP CONTACT, Female, Right Angle, 1mm Pitch, Locking ZIF", Contact Resistance=10mR, Flammability Rating="UL94 V-0", Insulation Color=Natural, Insulation Resistance=1GR, Manufacturer="TE Connectivity", Max Operating Temperature=85°C, Min Operating Temperature=-40°C
J11: library part J0335-A.3, "CONN header 2.54mm TH Male 1x4 pitch with locking", Flammability Rating="UL94 V-0", Insulation Color=White, Manufacturer=Molex
L1: library part I0078-A.1, "IND 10uH 20%, max 85mR, IRMS 3.5A, Isat 7A, 7.3x6.6x3mm", Case Code (Metric)=7.3x6.6x3mm, Inductance=10µH, Manufacturer=K-WELL, Tolerance=20%
L2: library part I0048-A.3, "IND CHIP SMD 1207 47uH 10% 1 ELEMENT", Case Code (Imperial)=1207, DC Resistance (DCR)=920mR, Inductance=47µH, Manufacturer="Taiyo Yuden", Max Operating Temperature=105°C, Min Operating Temperature=-25°C, Test Frequency=2.52MHz, Tolerance=10%
PB1: library part B0001-A.7, "PUSHBUTTON WHITE NO ANCHORS", Color=White, Manufacturer=Switronic
R1: library part R0163-A.20, "RES CHIP 0603 1M 1% 1/10W", Case Code (Imperial)=0603, Manufacturer=Vishay, Power=100mW, Temperature Coefficient=100ppm, Tolerance=1%
R2 R116: library part R0090-A.22, "RES CHIP 0603 10k 5% 1/10W B.5k", Case Code (Imperial)=0603, Manufacturer=Vishay, Power=100mW, Temperature Coefficient=200ppm, Tolerance=5%
R3 R8 R9 R10 R38: library part R0096-A.22, "RES CHIP 0603 0R 1/10W", Case Code (Imperial)=0603, Manufacturer=Vishay, Power=100mW, Temperature Coefficient=0ppm, Tolerance=0%
R4 R6 R11 R95 R96: library part R0124-A.22, "RES CHIP 0603 470R 1% 1/10W", Case Code (Imperial)=0603, Manufacturer=Vishay, Power=100mW, Temperature Coefficient=100ppm, Tolerance=1%
R5 R7 R31: library part R0116-A.22, "RES CHIP 0603 100k 1% 1/10W", Case Code (Imperial)=0603, Manufacturer=Vishay, Power=100mW, Temperature Coefficient=100ppm, Tolerance=1%
R33 R35: library part R0117-A.22, "RES CHIP 0603 19k1 1% 1/10W", Case Code (Imperial)=0603, Manufacturer=Vishay, Power=100mW, Temperature Coefficient=100ppm, Tolerance=1%
R36: library part R0220-A.15, "RES CHIP 0603 4k7 1% 1/10W", Case Code (Imperial)=0603, Manufacturer=Yageo, Power=100mW, Temperature Coefficient=100ppm, Tolerance=1%
SW2: library part S0022-A.4, "SWITCH DIP NORMALLY OPEN", Contact Resistance=100mR, Current Rating=25mA, Manufacturer="CTS Corporation", Max Operating Temperature=85°C, Max Voltage Rating (DC)=24V, Min Operating Temperature=-55°C, Package Quantity=145
U1: library part U0114-A.7, "IC CAN TRANSCEIVER 1Mbps STBY 5.25V SOIC8", Manufacturer=NXP
U2: library part U0296-A.3, "IC EEPROM, 32KX1, I2C, 1.7V TO 5.5V, SOIC8", Manufacturer="ON Semiconductor"
U7: library part U0241-A.6, "IC BUCK VIN 3V8 to 32V Iout 4A duty 100% fsw 500kHz TSOT26", Manufacturer="Diodes Incorporated"

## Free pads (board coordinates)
  round 1 hole 2.7 unplated paste-5 mask+2.5: FIXING(3.5,3.501) FIXING(3.5,52.499) FIXING(61.5,3.5) FIXING(61.5,52.499)

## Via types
v1: diameter 0.6, hole 0.3, TOP to BOTTOM, tented both sides, 246 vias

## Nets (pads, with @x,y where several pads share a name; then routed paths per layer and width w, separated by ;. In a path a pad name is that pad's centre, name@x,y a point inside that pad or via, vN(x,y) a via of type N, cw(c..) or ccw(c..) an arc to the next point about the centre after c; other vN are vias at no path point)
+3V3_PORTENTA: C4.1 C5.1 J2.23 J2.34 J2.43 J2.69 J3.1 J5.1 J5.17 J6.13 J10.15 PB1.2 R7.2 R8.2 R9.2 R10.2 R95.2 R116.2 SW2.3 SW2.4 U1.5 U2.8 | length 182.9
  TOP w0.2: J2.23@23.173,19.32 24.2,19.32 ; J2.43@23.173,23.32 24.2,23.32 ; J2.69@23.173,28.52 24.2,28.52 ; 25.225,21.32 J2.34@26.253,21.32 ; R7.2@51.236,27.191 R7.2@51.28,27.191 51.914,27.191 52.28,27.556 52.28,33.191 51.855,33.616 C5.1@51.28,33.616
  TOP w0.3: v1@24.079,22.802 24.123,22.802 v1(24.205,22.72) ; U1.5@34.075,10.895 35.323,10.895 35.41,10.809 ; C4.1@34.1,9.2 35.1,9.2 35.41,9.51 35.41,10.809 ; v1(35.391,13.223) 35.41,13.205 35.41,10.809 ; 52.808,5.5 52.808,3.542 J6.13@54.09,2.26
  TOP w0.4: 2.111,44.56 J3.1@3.165,44.56 ; 5.3,29.72 J10.15@6.9,29.72 ; PB1.2@5.962,8.97 7.362,8.97 8.162,9.77 ; R10.2@40.205,30.566 R9.2@40.205,31.966 R8.2@40.205,33.366 40.205,34.051 40.458,34.304 49.029,34.304 ; v1(49,38.6) 49.029,38.571 49.029,34.304 ; U2.8@49.012,33.309 50.223,33.309 50.53,33.616 C5.1@51.28,33.616 ; U2.8@49.029,33.326 49.029,34.304 ; 53.803,42 53.803,37.297 v1(54.7,36.4) v1(61.2,29.9) ; SW2.4@54.9,42.081 53.833,42.081 53.803,42.051 53.803,43.089 54.065,43.351 SW2.3@54.9,43.351 ; v1(77.193,29.113) 77.196,29.116 77.196,30.146 R116.2@77.2,30.15 R95.2@77.2,31.55
  TOP w0.7: 24.7,19.7 24.7,18.65 24.3,18.25 24.3,16.919 25.355,15.865 25.355,13.913 v1(25.34,13.898)
  TOP w1: v1@16.733,49 17.269,49.537 v1(19.811,49.537) ; J5.17@28.69,51.23 28.556,51.096 28.556,50.601 28.489,50.534 v1(28.489,48.404) 28.493,48.4 v1(34.518,48.4) ; v1(41.123,48.337) 44.2,45.261 v1(44.2,43.7)
  BOTTOM w0.4: v1(61.2,29.9) 63.067,29.9 66.087,26.88 73.387,26.88 73.594,27.087 73.599,27.087 74.043,27.531 74.043,28.351 74.805,29.113 v1(77.193,29.113)
  BOTTOM w1: J3.1@3.165,44.56 3.165,45.558 3.751,46.144 6.074,46.144 8.37,48.44 8.37,49.57 ; J5.1@8.37,51.2 8.37,49.57 ; v1(16.7,49) 16.13,49.57 8.37,49.57 ; v1(19.811,49.537) 20.602,49.537 21.735,48.404 v1(28.489,48.404) ; v1(34.518,48.4) 41.061,48.4 v1(41.123,48.337) ; v1(44.2,43.7) 44.2,43.4 v1(49,38.6) 51.217,36.383 54.683,36.383 v1(54.7,36.4)
  BOTTOM w1.2: v1(25.34,13.898) 26.015,13.223 v1(35.391,13.223) 46.578,13.223 v1(47.365,12.437)
+5V: C3.1 D1.4 J1.21 J1.24 J1.32 J1.41 J1.48 J4.1 J5.2 J5.4 J9.4 L2.1 R6.2 R38.2 U1.3 | length 202.1
  TOP w0.2: J1.48@66.353,21.32 67.02,21.32 67.3,21.6 67.3,23 ; J1.32@66.353,24.52 66.661,24.52 67.3,24.521 ; J1.24@66.353,26.12 66.803,26.12 67.406,25.517 v1(67.406,25.437) ; J1.41@69.433,22.52 68.828,22.52 68.348,23 67.3,23 ; J1.21@69.433,26.52 68.489,26.52 v1(67.406,25.437) ; 67.3,23 67.3,24.521 ; 67.3,24.521 67.406,24.627 v1(67.406,25.437)
  TOP w0.3: R6.2@9.212,3.86 10.549,3.86 10.812,3.596 10.812,2.344 11.863,1.293 21.229,1.293 J9.4@23.437,3.501 ; C3.1@26.646,12.315 26.794,12.167 U1.3@28.623,12.167
  TOP w0.4: v1(66.2,12.1) 66.899,12.1 D1.4@66.943,12.056 66.943,12.722 67.34,13.119 71.54,13.119 72.7,11.959 72.7,7.7 75.225,5.175 J4.1@75.225,4.92
  TOP w0.5: J9.4@23.437,3.501 25.224,5.288 25.224,11.672 25.868,12.315 C3.1@26.646,12.315 ; R38.2@24.112,36.669 24.187,36.669 24.808,37.29 v1(24.813,37.29)
  TOP w2: v1(54.7,20.5) 54.7,26.117 v1(54.707,26.125) 54.707,29.693 v1(54.7,29.7)
  BOTTOM w1: v1(54.707,26.125) 65.246,26.125 65.933,25.437 v1(67.406,25.437)
  BOTTOM w2: J9.4@23.437,3.501 23.437,6.408 20.68,9.166 8.28,9.166 5.38,12.066 5.38,23.766 7.38,25.766 11.18,25.766 13.58,28.166 13.58,35.037 15.847,37.305 v1@24.798,37.305 ; v1(24.813,37.29) 24.813,37.744 24.156,38.4 24.156,43.096 26.66,45.6 v1(29.4,45.6) ; v1(36.964,44.779) 40.395,44.779 54.7,30.474 v1(54.7,29.7) ; v1(54.7,20.5) 54.7,13 56.948,10.752 64.852,10.752 v1(66.2,12.1)
A0_1: J2.73 J6.1 | length 46.3
  TOP w0.15: J2.73@23.173,29.32 24.128,29.32 25.697,30.889 29.975,30.889 44.293,16.571 44.293,8.457 v1(44.798,7.952)
  BOTTOM w0.15: J6.1@38.85,2.26 40.109,3.519 42.055,3.519 42.537,4.001 42.537,6.5 43.988,7.952 v1(44.798,7.952)
A1_1: J2.75 J6.2 | length 43.6
  TOP w0.15: J2.75@23.173,29.72 23.962,29.72 25.443,31.201 30.229,31.201 44.682,16.747 44.682,10.626 44.884,10.424 v1(44.884,9.207)
  BOTTOM w0.15: J6.2@38.85,4.8 43.258,9.208 v1(44.884,9.207) v1(44.884,9.207)
A2_1: J2.77 J6.3 | length 46.8
  TOP w0.15: J2.77@23.173,30.12 23.797,30.12 25.161,31.484 30.511,31.484 44.959,17.036 44.959,10.937 46.5,9.396 v1(46.5,7.7)
  BOTTOM w0.15: J6.3@41.39,2.26 42.826,3.696 42.826,5.689 43.502,6.365 45.165,6.365 v1(46.5,7.7)
A3_1: J2.79 J6.4 | length 46.1
  TOP w0.15: J2.79@23.173,30.52 23.631,30.52 24.879,31.768 30.793,31.768 45.359,17.202 45.359,11.141 v1(47.3,9.2)
  BOTTOM w0.15: J6.4@41.39,4.8 41.39,6.154 43.702,8.465 46.565,8.465 v1(47.3,9.2)
A4_1: J2.74 J6.5 | length 36.2
  TOP w0.15: J2.74@26.253,29.32 29.325,29.32 42.148,16.497 42.148,6.163 42.628,5.683 42.628,3.526 43.894,2.26 J6.5@43.93,2.26
A5_1: J2.76 J6.6 | length 34.1
  TOP w0.15: J2.76@26.253,29.72 29.491,29.72 42.695,16.516 42.695,6.454 43.93,5.219 J6.6@43.93,4.8
A6_1: J2.78 J6.7 | length 38.2
  TOP w0.15: J2.78@26.253,30.12 29.657,30.12 43.195,16.582 43.195,7.543 45.237,5.501 45.237,3.493 J6.7@46.47,2.26
A7_1: J2.80 J6.8 | length 36.2
  TOP w0.15: J2.80@26.253,30.52 29.822,30.52 43.695,16.647 43.695,7.805 46.47,5.03 J6.8@46.47,4.8
BOOT_1: BOOT_PUSHBUTTON.X J2.1 J2.48 PB1.1 R11.2 | length 69.2
  TOP w0.15: v1@22.4,14.3 22.4,14.8 22.52,14.92 J2.1@23.173,14.92 ; J2.48@26.253,24.12 27.072,24.12 27.393,23.799 v1(29.3,23.799) ; v1(27.113,14.878) 30.937,18.702 32.02,18.702 v1(32.026,18.696)
  TOP w0.2: PB1.1@1.4,8.97 v1(3.331,8.97) 6.941,5.36 R11.2@7.662,5.36 ; R11.2@7.662,5.435 8.787,6.56 12.972,6.56 14.621,4.912 14.621,2.012 14.962,1.67 20.962,1.67 21.699,2.407 21.699,4.307 22.462,5.07 23.562,5.07 24.462,5.97 v1(24.462,7.77) ; v1(19.562,11.47) 19.566,11.47 v1(22.396,14.3) v1@22.4,14.3
  BOTTOM w0.15: v1(22.396,14.3) 22.9,14.3 23.715,15.115 26.82,15.115 27.058,14.878 v1(27.113,14.878) ; v1(29.3,23.799) 29.894,23.799 30.092,23.601 30.651,23.601 33.108,21.144 33.108,19.784 32.496,19.173 32.026,18.702 v1(32.026,18.696)
  BOTTOM w0.2: BOOT_PUSHBUTTON.X@2,9 2.015,8.985 3.316,8.985 v1(3.331,8.97) ; v1(19.562,11.47) 20.762,11.47 v1(24.462,7.77)
BT_SEL_1: BT_SEL.X J2.3 SW2.1 | length 74.8
  TOP w0.15: J2.3@23.173,15.32 23.598,15.32 24.13,14.788 v1(24.13,14.41) ; v1(48.1,14.1) 49.1,14.1 51.4,11.8 60,11.8 61.263,13.063 v1(61.263,16.363) 61.802,16.902 61.802,30.516 59,33.318 59,37.896 v1(58.996,37.901) 58.996,40.996 60.081,42.081 SW2.1@62.52,42.081
  BOTTOM w0.15: v1(24.13,14.41) 24.516,14.796 25.916,14.796 26.657,14.055 48.055,14.055 v1(48.1,14.1) ; v1(58.996,37.901) 58.998,37.899 58.998,37.002 BT_SEL.X@59,37
CAM.CK_1_N: J2.20 J10.8 | length 29.7
  TOP w0.2: J2.20@26.253,18.52 27.416,18.52 27.824,18.929 28.403,18.929 28.567,19.092 v1(28.675,19.092)
  TOP w0.21: J10.8@6.9,22.72 7.1,22.92 7.925,22.92 8.045,23.04 16.619,23.04 cw(c16.619,22.473) 17.186,22.473 17.186,21.833 v1(17.04,21.687)
  BOTTOM w0.2: v1(17.04,21.687) 17.229,21.876 17.229,22.139 cw(c18.065,22.139) 18.065,22.975 21.233,22.975 cw(c21.233,21.921) 22.288,21.921 22.288,20.517 ccw(c22.735,20.517) 22.735,20.07 26.659,20.07 cw(c26.659,19.346) 27.383,19.346 ccw(c27.826,19.346) 27.826,18.904 28.378,18.904 28.567,19.092 v1(28.675,19.092)
CAM.CK_1_P: J2.18 J10.9 | length 29.8
  TOP w0.2: J2.18@26.253,18.12 27.581,18.12 27.99,18.529 28.403,18.529 28.567,18.365 v1(28.675,18.365)
  TOP w0.21: J10.9@6.9,23.72 7.1,23.52 7.925,23.52 8.045,23.4 8.188,23.4 16.619,23.4 cw(c16.619,22.473) 17.546,22.473 17.546,21.909 v1(17.767,21.687)
  BOTTOM w0.2: v1(17.767,21.687) 17.579,21.876 17.579,22.139 cw(c18.065,22.139) 18.065,22.625 21.233,22.625 cw(c21.233,21.921) 21.938,21.921 21.938,20.517 ccw(c22.735,20.517) 22.735,19.72 22.964,19.72 26.659,19.72 cw(c26.659,19.346) 27.033,19.346 ccw(c27.826,19.346) 27.826,18.554 28.378,18.554 28.567,18.365 v1(28.675,18.365)
CAM.D0_1_N: J2.16 J10.2 | length 29.7
  TOP w0.2: v1(25.2,17.884) 25.308,17.884 25.497,17.695 25.8,17.695 25.825,17.72 J2.16@26.253,17.72
  TOP w0.21: J10.2@6.9,16.72 7.1,16.92 7.925,16.92 8.045,17.04 8.331,17.04 11.165,17.04 13.036,17.04 cw(c13.036,16.427) 13.649,16.427 13.649,13.821 ccw(c14.622,13.821) 15.595,13.821 15.595,16.427 cw(c16.208,16.427) 16.208,17.04 18.465,17.04 20.505,17.04 cw(c20.505,16.566) 20.98,16.566 20.98,15.855 20.796,15.671 v1@20.796,15.574
  BOTTOM w0.21: v1(20.796,15.566) 21.02,15.789 21.02,16.466 cw(c22.254,16.466) 22.254,17.7 25.017,17.7 ccw(c25.017,17.884) v1(25.2,17.884)
CAM.D0_1_P: J2.14 J10.3 | length 29.7
  TOP w0.2: v1(25.2,17.157) 25.308,17.157 25.497,17.345 25.8,17.345 25.825,17.32 J2.14@26.253,17.32
  TOP w0.21: J10.3@6.9,17.72 7.1,17.52 7.925,17.52 8.045,17.4 8.331,17.4 8.48,17.4 11.165,17.4 13.036,17.4 cw(c13.036,16.427) 14.009,16.427 14.009,13.821 ccw(c14.622,13.821) 15.235,13.821 15.235,16.427 cw(c16.208,16.427) 16.208,17.4 18.465,17.4 20.655,17.4 cw(c20.655,16.715) 21.34,16.715 21.34,15.749 v1(21.523,15.566)
  BOTTOM w0.21: v1(21.523,15.566) 21.38,15.709 21.38,16.466 cw(c22.254,16.466) 22.254,17.34 25.017,17.34 cw(c25.017,17.157) v1(25.2,17.157)
CAM.D1_1_N: J2.12 J10.5 | length 29.7
  TOP w0.2: J2.12@26.253,16.92 26.727,16.92 26.752,16.895 27.295,16.895 27.568,17.168 27.741,17.168 v1(28.1,17.527)
  TOP w0.21: J10.5@6.9,19.72 7.1,19.92 7.925,19.92 8.045,20.04 8.658,20.04 cw(c8.658,19.201) 9.251,19.794 9.861,19.185 ccw(c10.878,20.202) 10.878,18.764 12.755,18.764 13.04,18.764 ccw(c13.04,19.737) 14.013,19.737 14.013,20.066 cw(c14.626,20.066) 15.239,20.066 15.239,19.737 ccw(c16.212,19.737) 16.212,18.764 18.215,18.764 19.285,18.764 ccw(c19.285,19.402) 19.923,19.402 19.923,19.877 20.107,20.06 v1(20.107,20.166)
  BOTTOM w0.2: v1(20.107,20.166) 19.88,19.939 19.88,19.366 ccw(c20.23,19.366) 20.23,19.016 25.55,19.016 cw(c25.55,17.829) 26.737,17.829 ccw(c27.238,17.829) 27.238,17.327 27.792,17.327 27.992,17.527 v1(28.1,17.527)
CAM.D1_1_P: J2.10 J10.6 | length 29.5
  TOP w0.2: J2.10@26.253,16.52 26.727,16.52 26.752,16.545 27.44,16.545 27.647,16.753 28.071,16.753 v1(28.109,16.791)
  TOP w0.21: J10.6@6.9,20.72 7.1,20.52 7.925,20.52 8.045,20.4 8.331,20.4 8.659,20.4 cw(c8.659,19.204) 9.505,20.05 10.114,19.441 ccw(c10.88,20.207) 10.88,19.124 12.755,19.124 13.04,19.124 ccw(c13.04,19.737) 13.653,19.737 13.653,20.066 cw(c14.626,20.066) 15.599,20.066 15.599,19.737 ccw(c16.212,19.737) 16.212,19.124 18.215,19.124 19.136,19.124 ccw(c19.136,19.551) 19.563,19.551 19.563,19.877 19.38,20.06 v1(19.38,20.166)
  BOTTOM w0.2: v1(19.38,20.166) 19.53,20.016 19.53,19.366 ccw(c20.23,19.366) 20.23,18.666 25.55,18.666 cw(c25.55,17.829) 26.387,17.829 ccw(c27.238,17.829) 27.238,16.977 27.815,16.977 28.001,16.791 v1(28.109,16.791)
CAM.D2_1_N: J2.8
CAM.D2_1_P: J2.6
CAM.D3_1_N: J2.4
CAM.D3_1_P: J2.2
CAM.HS_1: J2.22
CAN1.RX_1: CANRX.X J1.51 U1.4 | length 100.4
  TOP w0.15: v1(17.18,34.466) 17.704,33.942 18.296,33.942 18.853,34.498 34.318,34.498 50.699,18.117 56.014,18.117 56.995,19.099 56.995,19.994 v1(57.695,20.694) ; U1.4@28.625,10.895 29.503,10.895 30.361,11.752 30.361,14.511 30.925,15.075 30.925,16.273 32.805,18.153 32.805,19.025 32.348,19.481 31.588,19.481 31.237,19.832 29.842,19.832 v1(29.809,19.799) ; v1(67.878,20.34) 68,20.34 68.181,20.52 J1.51@69.433,20.52
  BOTTOM w0.15: v1(17.18,34.466) 17.482,34.164 17.482,28.233 20.872,24.843 22.551,24.843 23.299,24.095 24.463,24.095 25.137,23.421 26.279,23.421 29.809,19.891 v1(29.809,19.799) 30.281,19.328 30.281,17.511 30,17.23 CANRX.X@30,17 ; v1(57.695,20.694) 57.7,20.699 67.379,20.699 67.602,20.476 67.634,20.476 67.77,20.34 v1(67.878,20.34)
CAN1.TX_1: CANTX.X J1.49 U1.1 | length 95
  TOP w0.15: v1(17.98,34.466) 18.428,34.466 18.738,34.775 34.433,34.775 50.814,18.394 55.899,18.394 56.718,19.213 56.718,20.444 v1(57.7,21.426) ; U1.1@28.625,14.705 29.855,14.705 30.525,15.375 30.525,16.265 32.528,18.267 32.528,18.91 32.24,19.198 31.09,19.198 30.959,19.33 v1(30.837,19.33) ; v1(67.684,21.104) 67.806,21.104 67.99,20.92 J1.49@69.433,20.92
  BOTTOM w0.15: v1(17.98,34.466) 17.98,28.127 20.987,25.12 22.666,25.12 23.414,24.372 24.578,24.372 25.244,23.706 26.452,23.706 29.858,20.3 30.2,20.3 30.782,19.718 30.782,19.384 v1(30.837,19.33) 30.837,18.163 CANTX.X@32,17 ; v1@57.649,21.477 v1(57.7,21.426) 58.15,20.976 67.371,20.976 67.413,21.018 67.598,21.018 v1(67.684,21.104)
CD: J1.67 J7.CD1 | length 13.7
  TOP w0.15: v1(68.522,18.902) 68.522,17.781 68.983,17.32 J1.67@69.433,17.32 ; J7.CD1@71.1,28.449 71.14,28.409 71.14,27.037 71.262,26.915 71.262,21.963 71.14,21.841 v1(71.14,21.719)
  BOTTOM w0.15: v1(68.522,18.902) 69.745,20.125 69.745,21.496 70.071,21.822 70.915,21.822 71.018,21.719 v1(71.14,21.719)
CLK: J1.55 J7.5 | length 13.3
  TOP w0.15: J1.55@69.433,19.72 71.46,19.72 v1(73.34,21.6) ; v1(78.614,21.592) 81.893,21.592 J7.5@81.9,21.599
  BOTTOM w0.15: v1(73.34,21.6) 73.344,21.596 78.61,21.596 v1(78.614,21.592)
CMD: J1.57 J7.3 | length 14.3
  TOP w0.15: J1.57@69.433,19.32 73.745,19.32 78.224,23.799 J7.3@81.9,23.799
d0: J1.59 J7.7 | length 12.7
  TOP w0.15: J1.59@69.433,18.92 80.282,18.92 80.76,19.399 J7.7@81.9,19.399
D1: J1.61 J7.8 | length 12.6
  TOP w0.15: J1.61@69.433,18.52 80.323,18.52 80.545,18.299 J7.8@81.9,18.299
D2: J1.63 J7.1 | length 16
  TOP w0.15: J1.63@69.433,18.12 70.491,18.12 70.678,17.933 v1(70.8,17.933) ; v1(72.637,19.901) 78.735,25.999 J7.1@81.9,25.999
  BOTTOM w0.15: v1(70.8,17.933) 70.8,18.055 70.956,18.211 70.956,18.22 v1(72.637,19.901)
D3: J1.65 J7.2 | length 15.7
  TOP w0.15: J1.65@69.433,17.72 70.046,17.72 70.335,17.431 71.085,17.431 v1(71.58,17.926) ; v1(73.437,19.901) 78.435,24.899 J7.2@81.9,24.899
  BOTTOM w0.15: v1(71.58,17.926) 71.58,17.985 73.437,19.842 v1(73.437,19.901)
DSI_CK_N: J1.20
DSI_CK_P: J1.18
DSI_D0_N: J1.16
DSI_D0_P: J1.14
DSI_D1_N: J1.12
DSI_D1_P: J1.10
DSI_D2_N: J1.8
DSI_D2_P: J1.6
DSI_D3_N: J1.4
DSI_D3_P: J1.2
ETH_A_N: J1.3 J8.10 | length 24.4
  TOP w0.2: J1.3@69.433,30.12 70.289,30.12 70.64,30.472 70.64,31.019
  TOP w0.25: 70.64,31.019 70.64,36.995 cw(c73.98,36.995) 71.618,39.357 72.439,40.178 ccw(c70.36,42.257) 73.3,42.257 73.3,49.177 ccw(c71.879,49.177) 72.884,50.182 72.865,50.201 ccw(c71.901,49.237) 71.901,50.6 71.9,50.6 71.113,51.387 ccw(c70.925,51.199) J8.10@70.925,51.465
ETH_A_P: J1.1 J8.9 | length 25.3
  TOP w0.2: J1.1@69.433,30.52 69.84,30.52 70.123,30.52 70.24,30.637 70.24,31.019
  TOP w0.25: J8.9@68.385,50.195 68.39,50.2 71.9,50.2 cw(c71.9,49.234) 72.583,49.917 72.6,49.9 cw(c71.876,49.176) 72.9,49.176 72.9,42.257 cw(c70.36,42.257) 72.156,40.461 71.335,39.64 ccw(c73.98,36.995) 70.24,36.995 70.24,31.019
ETH_B_N: J1.7 J8.8 | length 26.6
  TOP w0.2: J1.7@69.433,29.32 70.139,29.32 70.14,29.319
  TOP w0.25: 70.14,29.319 70.719,29.319 ccw(c70.719,30.187) 71.587,30.187 71.587,36.935 cw(c74.127,36.935) 72.331,38.731 74.603,41.003 ccw(c72.523,43.081) 75.463,43.063 75.463,45.322 cw(c75.743,45.322) 75.545,45.52 v1@75.56,45.534 ; v1@75.56,45.535 ccw(c75.398,45.696) v1(75.627,45.696)
  BOTTOM w0.25: J8.8@70.925,48.925 ccw(c71.79,48.925) 71.79,48.06 74.394,48.06 cw(c74.394,46.827) 75.627,46.827 v1(75.627,45.696)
